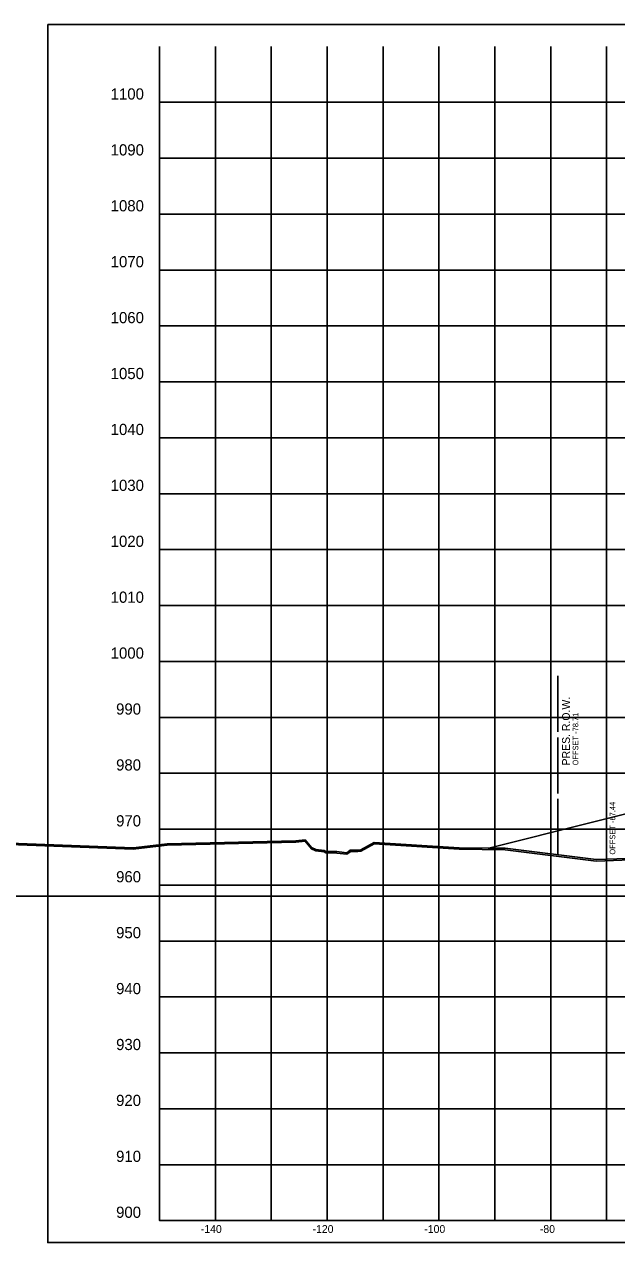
# Model space of a CAD drawing. Extents: x 5868 to 6683, y 2883 to 19120.
# Drawn here: x 6019.6 to 6125.6, y 16883.1 to 17101 of the extents above; entities that cross this region are included whole.
import ezdxf

# ---------------------------------------------------------------- set-up
doc = ezdxf.new("R2010")
doc.units = 0
for name, color, linetype in [('DESIGN - EARTHWORK - Shapes', 7, 'Continuous'), ('DESIGN - SHEET - Corner Text', 7, 'Continuous'), ('DESIGN - SHEET - Light Grid', 7, 'Continuous'), ('DESIGN - SHEET - Linework', 7, 'Continuous'), ('DESIGN - SHEET - Plot Shape', 7, 'Continuous'), ('DESIGN - TYPICAL - Slope Tie Text', 7, 'Continuous'), ('SURVEY - GROUND - Bottom of Topsoil Layer', 7, 'Continuous'), ('SURVEY - GROUND - Top of Ground', 7, 'Continuous'), ('SURVEY - PROPERTY - ROW Lines', 7, 'Continuous'), ('SURVEY - PROPERTY - ROW Lines Text', 7, 'Continuous')]:
    doc.layers.add(name, color=color, linetype=linetype)

msp = doc.modelspace()

# ---------------------------------------------------------------- linework, layer by layer
at = {"layer": 'DESIGN - EARTHWORK - Shapes'}
for points in [[(6164.91, 16967.58), (6164.29, 16967.57), (6149.07, 16961.09), (6137.3, 16954.97), (6136.97, 16953.08), (6136.48, 16951.93), (6134.93, 16952.12), (6131.16, 16951.94), (6121.89, 16951.63), (6105.63, 16953.66), (6102.68, 16953.69), (6102.68, 16953.44), (6105.63, 16953.41), (6121.89, 16951.38), (6131.16, 16951.69), (6134.93, 16951.87), (6136.48, 16951.68), (6136.97, 16952.83), (6137.3, 16954.72), (6149.07, 16960.84)], [(6164.91, 16967.58), (6164.29, 16967.57), (6149.07, 16961.09), (6137.3, 16954.97), (6136.97, 16953.08), (6136.48, 16951.93), (6134.93, 16952.12), (6131.16, 16951.94), (6121.89, 16951.63), (6105.63, 16953.66), (6102.68, 16953.69), (6102.68, 16953.44), (6105.63, 16953.41), (6121.89, 16951.38), (6131.16, 16951.69), (6134.93, 16951.87), (6136.48, 16951.68), (6136.97, 16952.83), (6137.3, 16954.72), (6149.07, 16960.84)], [(6102.68, 16953.69), (6105.63, 16953.66), (6121.89, 16951.63), (6131.16, 16951.94), (6134.93, 16952.12), (6136.48, 16951.93), (6136.97, 16953.08), (6137.3, 16954.97), (6149.07, 16961.09), (6164.29, 16967.57), (6162.37, 16967.53), (6157.66, 16967.44)], [(6102.68, 16953.69), (6105.63, 16953.66), (6121.89, 16951.63), (6131.16, 16951.94), (6134.93, 16952.12), (6136.48, 16951.93), (6136.97, 16953.08), (6137.3, 16954.97), (6149.07, 16961.09), (6164.29, 16967.57), (6162.37, 16967.53), (6157.66, 16967.44)]]:
    msp.add_lwpolyline(points, close=True, dxfattribs=at)
at = {"layer": 'DESIGN - SHEET - Light Grid'}
msp.add_line((5893.78, 16945.07), (6193.78, 16945.07), dxfattribs=at)
at = {"layer": 'DESIGN - SHEET - Linework'}
for p, q in [((6053.78, 16887.07), (6053.78, 17097.07)), ((6063.78, 16887.07), (6063.78, 17097.07)), ((6073.78, 16887.07), (6073.78, 17097.07)), ((6083.78, 16887.07), (6083.78, 17097.07)), ((6093.78, 16887.07), (6093.78, 17097.07)), ((6103.78, 16887.07), (6103.78, 17097.07)), ((6113.78, 16887.07), (6113.78, 17097.07)), ((6123.78, 16887.07), (6123.78, 17097.07)), ((6043.78, 17087.07), (6343.78, 17087.07)), ((6043.78, 17077.07), (6343.78, 17077.07)), ((6043.78, 17067.07), (6343.78, 17067.07)), ((6043.78, 17057.07), (6343.78, 17057.07)), ((6043.78, 17047.07), (6343.78, 17047.07)), ((6043.78, 17037.07), (6343.78, 17037.07)), ((6043.78, 17027.07), (6343.78, 17027.07)), ((6043.78, 17017.07), (6343.78, 17017.07)), ((6043.78, 17007.07), (6343.78, 17007.07)), ((6043.78, 16997.07), (6343.78, 16997.07)), ((6043.78, 16987.07), (6343.78, 16987.07)), ((6043.78, 16977.07), (6343.78, 16977.07)), ((6043.78, 16967.07), (6343.78, 16967.07)), ((6043.78, 16957.07), (6343.78, 16957.07)), ((6043.78, 16947.07), (6343.78, 16947.07)), ((6043.78, 16937.07), (6343.78, 16937.07)), ((6043.78, 16927.07), (6343.78, 16927.07)), ((6043.78, 16917.07), (6343.78, 16917.07)), ((6043.78, 16907.07), (6343.78, 16907.07)), ((6043.78, 16897.07), (6343.78, 16897.07))]:
    msp.add_line(p, q, dxfattribs=at)
msp.add_lwpolyline([(6043.78, 17097.07), (6043.78, 16887.07), (6343.78, 16887.07), (6343.78, 17097.07)], dxfattribs=at)
at = {"layer": 'DESIGN - SHEET - Plot Shape'}
msp.add_lwpolyline([(6023.78, 17101.01), (6363.78, 17101.01), (6363.78, 16883.13), (6023.78, 16883.13)], close=True, dxfattribs=at)
at = {"layer": 'SURVEY - GROUND - Bottom of Topsoil Layer'}
msp.add_lwpolyline([(6015.4, 16954.39), (6039.07, 16953.52), (6045.17, 16954.2), (6068.16, 16954.74), (6069.83, 16954.94), (6070.95, 16953.58), (6071.76, 16953.22), (6073.26, 16953.01), (6073.56, 16952.84), (6075.53, 16952.81), (6077.27, 16952.58), (6077.91, 16953.05), (6079.27, 16953.07), (6079.82, 16953.12), (6082.16, 16954.46), (6097.41, 16953.49), (6105.63, 16953.41), (6121.89, 16951.38), (6131.16, 16951.69)], dxfattribs=at)
at = {"layer": 'SURVEY - GROUND - Top of Ground'}
msp.add_lwpolyline([(6015.4, 16954.64), (6039.07, 16953.77), (6045.17, 16954.45), (6068.16, 16954.99), (6069.83, 16955.19), (6070.95, 16953.83), (6071.76, 16953.47), (6073.26, 16953.26), (6073.56, 16953.09), (6075.53, 16953.06), (6077.27, 16952.83), (6077.91, 16953.3), (6079.27, 16953.32), (6079.82, 16953.37), (6082.16, 16954.71), (6097.41, 16953.74), (6105.63, 16953.66), (6121.89, 16951.63), (6131.16, 16951.94)], dxfattribs=at)
at = {"layer": 'SURVEY - PROPERTY - ROW Lines'}
for p, q in [((6115.07, 16974.48), (6115.07, 16984.48)), ((6115.07, 16963.48), (6115.07, 16973.48)), ((6115.07, 16952.48), (6115.07, 16962.48))]:
    msp.add_line(p, q, dxfattribs=at)

# ---------------------------------------------------------------- texts
at = {"layer": 'DESIGN - SHEET - Corner Text'}
for s, height, p in [('1100', 2, (6035.03, 17087.57)), ('1090', 2, (6035.03, 17077.57)), ('1080', 2, (6035.03, 17067.57)), ('1070', 2, (6035.03, 17057.57)), ('1060', 2, (6035.03, 17047.57)), ('1050', 2, (6035.03, 17037.57)), ('1040', 2, (6035.03, 17027.57)), ('1030', 2, (6035.03, 17017.57)), ('1020', 2, (6035.03, 17007.57)), ('1010', 2, (6035.03, 16997.57)), ('1000', 2, (6035.03, 16987.57)), ('990', 2, (6036, 16977.57)), ('980', 2, (6036, 16967.57)), ('970', 2, (6036, 16957.57)), ('960', 2, (6036, 16947.57)), ('950', 2, (6036, 16937.57)), ('940', 2, (6036, 16927.57)), ('930', 2, (6036, 16917.57)), ('920', 2, (6036, 16907.57)), ('910', 2, (6036, 16897.57)), ('900', 2, (6036, 16887.57)), ('-140', 1.4, (6051.16, 16884.87)), ('-120', 1.4, (6071.16, 16884.87)), ('-100', 1.4, (6091.16, 16884.87)), ('-80', 1.4, (6111.84, 16884.87))]:
    msp.add_text(s, height=height, dxfattribs=at).set_placement(p)
at = {"layer": 'DESIGN - TYPICAL - Slope Tie Text'}
msp.add_text('OFFSET -67.44', height=1, rotation=90, dxfattribs=at).set_placement((6125.34, 16952.53))
at = {"layer": 'SURVEY - PROPERTY - ROW Lines Text'}
for s, height, p in [('PRES. R.O.W.', 1.4, (6117.22, 16968.48)), ('OFFSET -78.71', 1, (6118.72, 16968.48))]:
    msp.add_text(s, height=height, rotation=90, dxfattribs=at).set_placement(p)

doc.saveas('drawing.dxf')
